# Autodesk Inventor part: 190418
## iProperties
Shininess: 69.0
Length Units: 11269
Angle Units: 11279
Time Units: 11290
Mass Units: 11284
Length Display Precision: 3
Angle Display Precision: 2
Compacted: True
Company: Pneumax S.p.A.
Part Number: 190418
Material: Default
Description: RACCORDO AD L FISSO Ø4 G1/8"
Document SubType Name: Modellazione
Catalog Web Link: www.pneumaxspa.com
Density: 1.59
Volumn: 0.8648857994912436
Area: 17.092995283760587
PropertySet Name: Model Information
Control State: 0
Master: False
Checked Out: False
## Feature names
1. Revolution6
2. Revolution7
3. Revolution10
4. Estrusione10 [Extrusion]
5. Chamfer10
6. Foro6 [Hole]
7. Extrusion9
8. Mirror2
